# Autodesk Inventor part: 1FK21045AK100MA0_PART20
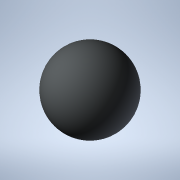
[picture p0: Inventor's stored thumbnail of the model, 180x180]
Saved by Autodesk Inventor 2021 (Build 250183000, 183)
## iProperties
Created: 2025-04
Part Number: 1FK21045AK100MA0_PART20
Material: Generic
Catalog Web Link: www.3dfindit.com
Description: -Servo synchronous motor
Document SubType Name: Modeling
Designer: psAdmin
Mass: 0.137258 g
Surface Area: 1.2868 cm^2
Volume: 0.137258 cm^3
Density: 1 g/cm^3
Appearance: PSOLRGB-212-217-219
Category: PARTsolutions
Title: 1FK21045AK100MA0_PART20
Author: Cadenas PARTsolutions
Comments: Servo synchronous motor
Sending System: PARTsolutions
Preprocessor: ST-DEVELOPER v19.3
PSOL_IDENT_0: {$CADENAS_DATA/23d-libs/siemens_ag/_cat_/e0/5f/1fk21045ak100ma0.prj},216 {VTYP=3D},{NB=1FK21045AK100
PSOL_IDENT_1: MA0_PART20},{LINA=1FK21045AK100MA0_PART20},{NN=1FK21045AK100MA0_PART20},{NOPRJ=TRUE},{DATE=19.08.202
PSOL_IDENT_2: 5 14:01:03},{GEOMDATE=30.07.2025 02:01:57},{VERSION=},{LINEID=10},{WBVAR=},{WBNUMERIC=}  {NB=1FK2104
PSOL_IDENT_3: 5AK100MA0_PART20},{LINA=1FK21045AK100MA0_PART20},{KT=DUMMY},{PREVIEW=../../../_pool_/0f/2c/p_d211_xx
PSOL_IDENT_4: _00438j.png},{DESCSHORT=SIMOTICS S-1FK2 HD, SINAMICS S210 3AC 400V-480V, 1.7 Nm, 6000 rpm},{DESCLONG=
PSOL_IDENT_5: SIMOTICS S-1FK2 HD servo motor M0=2.4 Nm; PN = 1.07 kW at nN=6000 rpm (380-480 V); PN = 0.75 kW at n
PSOL_IDENT_6: N=3000 rpm (200-240 V); with holding brake; degree of protection IP64; cylindrical shaft D19x40mm; a
PSOL_IDENT_7: bsolute encoder 22-bit + 12-bit multiturn (encoder AM22DQC); with OCC interface; plug size M17, rota
PSOL_IDENT_8: table; SIMOTICS S-1FK2 servomotorfor a wide range of uses in industrial environments. SIMOTICS S‑1FK
PSOL_IDENT_9: 2 servomotors are compact synchronous motors with a high dynamic performance that set themselves apa
PSOL_IDENT_10: rt as a result of their high power density, degree of protection and overload capability. The motors
PSOL_IDENT_11: are available in two variants: as High Dynamic variant (highest dynamic performance as a result of
PSOL_IDENT_12: the low intrinsic moment of inertia for applications demanding a high dynamic performance with low m
PSOL_IDENT_13: oved masses) - and as Compact variant (precise and stable closed-loop control for medium up to large
PSOL_IDENT_14: moved masses as a result of a medium intrinsic moment of inertia). SIMOTICSS‑1FK2 servomotors fully
PSOL_IDENT_15: exploit their strengths in a system with the SINAMICSS210 frequency converter and simple connection
PSOL_IDENT_16: using the one cable connection (OCC). Advantages include the short control and positioning times, f
PSOL_IDENT_17: ast and precise correction of disturbing quantities as well as stable control with a high dynamic pe
PSOL_IDENT_18: rformance. The servo motors can be configured to address a wide range of requirements. For example w
PSOL_IDENT_19: ith and without holding brake, IP64 or IP65 degree of protection, singleturn or multiturn absolute e
PSOL_IDENT_20: ncoders - to name just a few. Further, the servomotors are available in different shaft heights exte
PSOL_IDENT_21: nding from 20 to 100. A shaft sealing ring is available to achieve an IP65 degree of protection and
PSOL_IDENT_22: for subsequent mounting at the motor or as spare part. SIMOTICS - the optimum motor for each and eve
PSOL_IDENT_23: ry motion control application.},{INTNO=804766807114},{SUPPLIERALTNO=1FK2104-5AK10-0MA0},{MANUID=1FK2
PSOL_IDENT_24: 1045AK100MA0},{MANUNAME=Siemens},{MANUTYPEDESC=Synchronous motor 1FK2-HD 2,39 Nm},{AAU732=SIMOTICS},
PSOL_IDENT_25: {AAO057=S-1FK2},{AAU734=SIMOTICS S-1FK2 HD servo motor M0=2.4 Nm; PN = 1.07 kW at nN=6000 rpm (380-4
PSOL_IDENT_26: 80 V); PN = 0.75 kW at nN=3000 rpm (200-240 V); with holding brake; degree of protection IP64; cylin
PSOL_IDENT_27: drical shaft D19x40mm; absolute encoder 22-bit + 12-bit multiturn (encoder AM22DQC); with OCC interf
PSOL_IDENT_28: ace; plug size M17, rotatable;},{AAW338=Synchronous motor 1FK2-HD 2,39 Nm},{AAO742=SIMOTICS},{AAO663=
PSOL_IDENT_29: 4042948691236},{NOCUPEROU=1},{PRICEQUANTITY=1},{QUANTITYMIN=1},{QUANTITYINT=1},{CTN=85015100},{COO=D
PSOL_IDENT_30: E},{AAO676=1FK2104-5AK10-0MA0},{AAO677=Siemens AG},{ORDERUNIT=C62},{CONTENTUNIT=C62}
NB: 1FK21045AK100MA0_PART20
NT: Servo synchronous motor
NBSYN: $MANUID._PART20
LINA: 1FK21045AK100MA0_PART20
CATALOG: SIEMENS
PREVIEW: ../../../_pool_/0f/2c/p_d211_xx_00438j.png
DESCSHORT: SIMOTICS S-1FK2 HD, SINAMICS S210 3AC 400V-480V, 1.7 Nm, 6000 rpm
DESCLONG: SIMOTICS S-1FK2 HD servo motor M0=2.4 Nm; PN = 1.07 kW at nN=6000 rpm (380-480 V); PN = 0.75 kW at nN=3000 rpm (200-240 V); with holding brake; degree of protec
INTNO: 804766807114
SUPPLIERALTNO: 1FK2104-5AK10-0MA0
MANUID: 1FK21045AK100MA0
MANUNAME: Siemens
MANUTYPEDESC: Synchronous motor 1FK2-HD 2,39 Nm
AAU732: SIMOTICS
AAO057: S-1FK2
AAU734: SIMOTICS S-1FK2 HD servo motor M0=2.4 Nm; PN = 1.07 kW at nN=6000 rpm (380-480 V); PN = 0.75 kW at nN=3000 rpm (200-240 V); with holding brake; degree of protec
AAW338: Synchronous motor 1FK2-HD 2,39 Nm
AAO742: SIMOTICS
AAO663: 4042948691236.0
NOCUPEROU: 1
PRICEQUANTITY: 1
QUANTITYMIN: 1
QUANTITYINT: 1
CTN: 85015100
COO: DE
ARTICLENO: 1FK21045AK100MA0_PART20
BOMINFO: 1FK21045AK100MA0_PART20
CREATOR: CADENAS GmbH
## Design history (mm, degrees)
feature "2025_04_17_15_45_15_0090"
body "Solid1"
